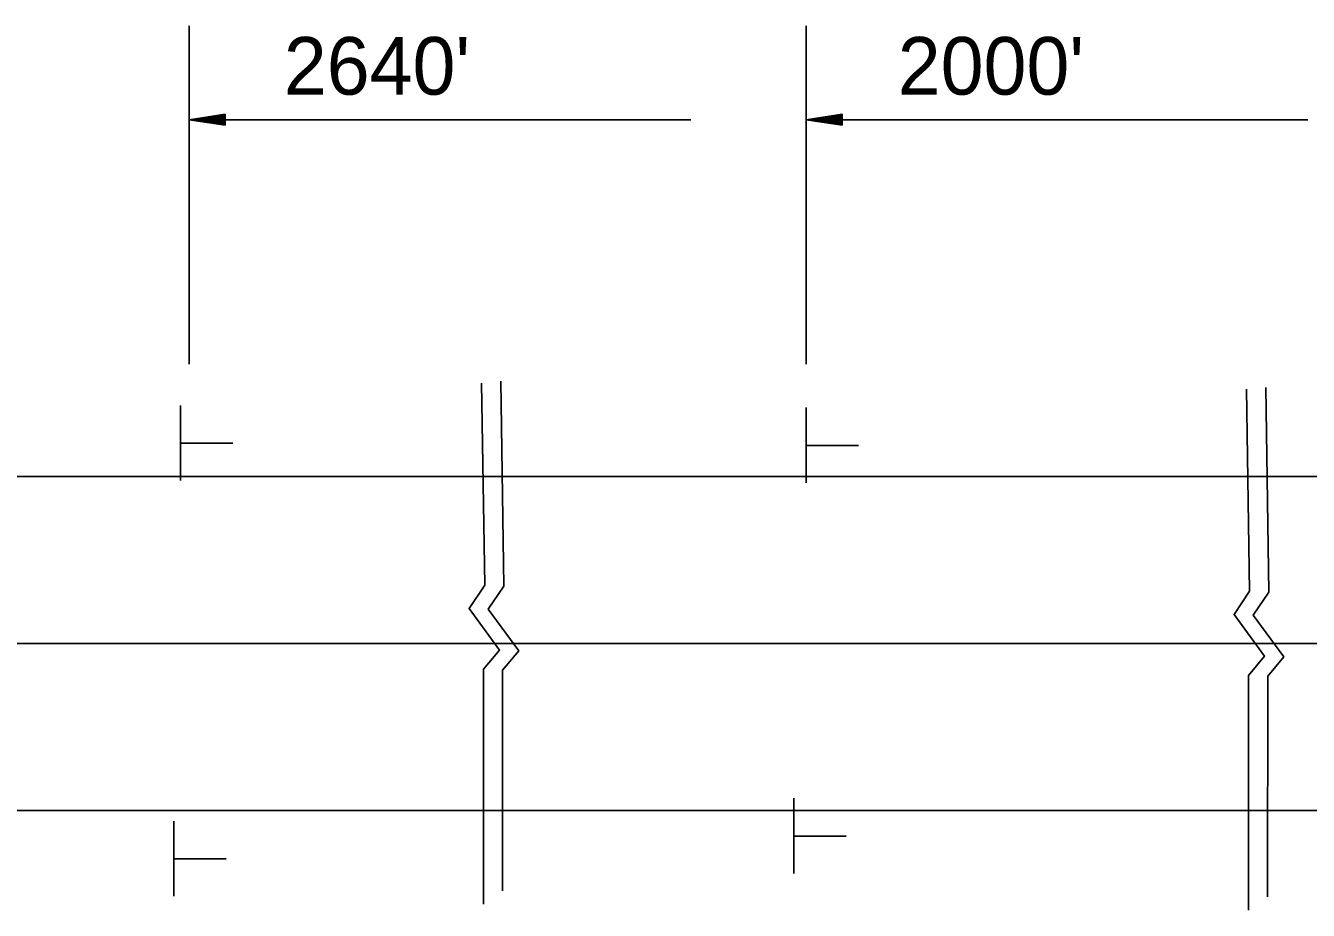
# Model space of a CAD drawing. Extents: x 1374897 to 1375063, y 381144 to 381251.
# Drawn here: x 1374944.82 to 1374958.16, y 381215.18 to 381224.39 of the extents above; entities that cross this region are included whole.
import ezdxf

# ---------------------------------------------------------------- set-up
doc = ezdxf.new("R2010")
doc.units = 0
doc.layers.add('Default', color=7, linetype='Continuous')

msp = doc.modelspace()

# ---------------------------------------------------------------- linework, layer by layer
at = {"layer": 'Default'}
for p, q in [((1374946.519, 381224.39), (1374946.519, 381220.869)), ((1374952.935, 381224.39), (1374952.935, 381220.869)), ((1374946.894, 381223.468), (1374946.519, 381223.411)), ((1374946.519, 381223.411), (1374951.738, 381223.411)), ((1374946.894, 381223.355), (1374946.519, 381223.411)), ((1374946.894, 381223.458), (1374946.582, 381223.411)), ((1374946.894, 381223.364), (1374946.582, 381223.411)), ((1374946.894, 381223.449), (1374946.646, 381223.411)), ((1374946.894, 381223.374), (1374946.646, 381223.411)), ((1374946.894, 381223.439), (1374946.709, 381223.411)), ((1374946.894, 381223.383), (1374946.709, 381223.411)), ((1374946.894, 381223.43), (1374946.772, 381223.411)), ((1374946.894, 381223.393), (1374946.772, 381223.411)), ((1374946.894, 381223.42), (1374946.835, 381223.411)), ((1374946.894, 381223.402), (1374946.835, 381223.411)), ((1374946.894, 381223.355), (1374946.894, 381223.468)), ((1374953.31, 381223.468), (1374952.935, 381223.411)), ((1374952.935, 381223.411), (1374958.154, 381223.411)), ((1374953.31, 381223.355), (1374952.935, 381223.411)), ((1374953.31, 381223.458), (1374952.998, 381223.411)), ((1374953.31, 381223.364), (1374952.998, 381223.411)), ((1374953.31, 381223.449), (1374953.062, 381223.411)), ((1374953.31, 381223.374), (1374953.062, 381223.411)), ((1374953.31, 381223.439), (1374953.125, 381223.411)), ((1374953.31, 381223.383), (1374953.125, 381223.411)), ((1374953.31, 381223.43), (1374953.188, 381223.411)), ((1374953.31, 381223.393), (1374953.188, 381223.411)), ((1374953.31, 381223.42), (1374953.251, 381223.411)), ((1374953.31, 381223.402), (1374953.251, 381223.411)), ((1374953.31, 381223.355), (1374953.31, 381223.468)), ((1374946.428, 381219.656), (1374946.428, 381220.438)), ((1374952.935, 381219.632), (1374952.935, 381220.415)), ((1374946.44, 381220.045), (1374946.974, 381220.045)), ((1374952.947, 381220.021), (1374953.481, 381220.021)), ((1374942.721, 381219.7), (1374948.918, 381219.7)), ((1374948.918, 381219.7), (1374955.003, 381219.7)), ((1374955.003, 381219.7), (1374963.663, 381219.7)), ((1374942.767, 381217.961), (1374948.885, 381217.961)), ((1374948.885, 381217.961), (1374955.003, 381217.961)), ((1374955.003, 381217.961), (1374963.663, 381217.961)), ((1374952.809, 381215.568), (1374952.809, 381216.35)), ((1374942.813, 381216.223), (1374948.851, 381216.223)), ((1374948.851, 381216.223), (1374956.285, 381216.223)), ((1374955.003, 381216.223), (1374964.581, 381216.223)), ((1374946.36, 381215.33), (1374946.36, 381216.112)), ((1374952.82, 381215.957), (1374953.354, 381215.957)), ((1374946.372, 381215.719), (1374946.906, 381215.719))]:
    msp.add_line(p, q, dxfattribs=at)
for points in [[(1374949.561, 381220.67), (1374949.593, 381218.567), (1374949.43, 381218.325), (1374949.747, 381217.892), (1374949.58, 381217.692), (1374949.58, 381215.247)], [(1374949.76, 381220.689), (1374949.793, 381218.558), (1374949.63, 381218.317), (1374949.947, 381217.884), (1374949.78, 381217.684), (1374949.78, 381215.387)], [(1374957.517, 381220.607), (1374957.549, 381218.504), (1374957.387, 381218.262), (1374957.703, 381217.829), (1374957.537, 381217.629), (1374957.536, 381215.184)], [(1374957.717, 381220.626), (1374957.749, 381218.495), (1374957.587, 381218.254), (1374957.903, 381217.821), (1374957.737, 381217.621), (1374957.736, 381215.324)]]:
    msp.add_lwpolyline(points, dxfattribs=at)

# ---------------------------------------------------------------- texts
for s, p in [("2640'", (1374947.504, 381223.672)), ("2000'", (1374953.889, 381223.672))]:
    msp.add_text(s, height=0.6, dxfattribs=at).set_placement(p)

doc.saveas('drawing.dxf')
